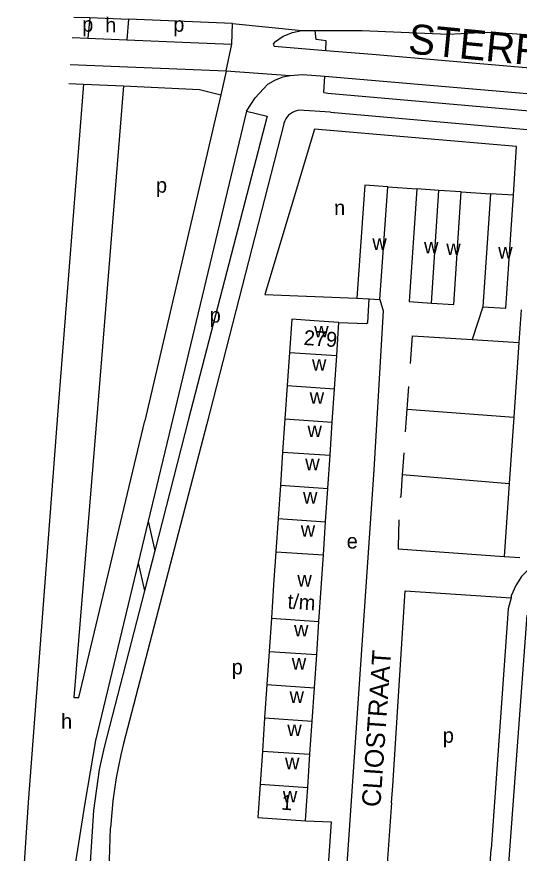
# Model space of a CAD drawing. Extents: x 161773 to 163836, y 384796 to 386521.
# Drawn here: x 161920.3 to 162054.9, y 386283.2 to 386507.1 of the extents above; entities that cross this region are included whole.
import ezdxf

# ---------------------------------------------------------------- set-up
doc = ezdxf.new("R2010")
doc.units = 0
for name, color, linetype in [('BLT_Basislijn', 7, 'Continuous'), ('BLT_Bebouwing', 7, 'Continuous'), ('BLT_Centroide', 7, 'Continuous'), ('BLT_Huisnummer_reeks', 7, 'Continuous'), ('BLT_Onderverdeling_panden', 7, 'Continuous'), ('BLT_Straatnaam', 7, 'Continuous'), ('BLT_Straatnaam_hoofdweg', 7, 'Continuous'), ('BLT_Vlakafsluiter', 7, 'Continuous')]:
    doc.layers.add(name, color=color, linetype=linetype)

msp = doc.modelspace()

# ---------------------------------------------------------------- linework, layer by layer
at = {"layer": 'BLT_Basislijn'}
for p, q in [((161935.63, 386507.05), (161939.87, 386506.89)), ((161939.87, 386506.89), (161939.37, 386501.38)), ((161939.87, 386506.89), (161950.28, 386506.48)), ((161950.28, 386506.48), (161949.83, 386500.95)), ((161935.17, 386501.56), (161939.37, 386501.38)), ((161939.37, 386501.38), (161949.83, 386500.95)), ((161949.83, 386500.95), (161966.84, 386500.23)), ((161934.64, 386494.33), (161976.44, 386492.65)), ((161976.43, 386492.6), (161974.94, 386486.21)), ((161976.44, 386492.65), (161976.43, 386492.6)), ((161996.87, 386491.69), (162002.79, 386491.19)), ((161938.19, 386489.12), (161931.36, 386401.7)), ((161934.27, 386489.3), (161938.19, 386489.12)), ((161938.19, 386489.12), (161948.92, 386488.61)), ((162002.53, 386486.84), (162002.79, 386491.19)), ((162002.79, 386491.19), (162077.21, 386484.92)), ((161948.92, 386488.61), (161941.93, 386402.27)), ((161974.94, 386486.21), (161954.62, 386399)), ((161981.83, 386481.82), (161962.23, 386399.97)), ((161987.41, 386480.49), (161966.35, 386399.44)), ((161981.83, 386481.82), (161987.41, 386480.49)), ((162004.3, 386481.62), (161995.88, 386482.11)), ((162004.3, 386481.62), (162059.08, 386476.74)), ((161991.85, 386478.49), (161971.19, 386398.18)), ((162019.69, 386461.58), (162027.41, 386461.04)), ((162039.33, 386460.24), (162047.16, 386459.74)), ((162045.16, 386429.52), (162042.3, 386420.71)), ((162055.37, 386428.67), (162054.77, 386419.92)), ((162054.77, 386419.92), (162053.39, 386399.97)), ((162024.87, 386402.1), (162025.32, 386408.17)), ((162024.42, 386396.04), (162024.87, 386402.1)), ((162024.87, 386402.1), (162053.39, 386399.97)), ((161931.36, 386401.7), (161923.36, 386296.84)), ((162053.39, 386399.97), (162052.17, 386382.22)), ((161971.19, 386398.18), (161948.93, 386312.61)), ((162024, 386390.4), (162023.64, 386385.56)), ((162023.55, 386384.58), (162023.13, 386378.77)), ((162023.64, 386385.56), (162023.55, 386384.58)), ((162023.55, 386384.58), (162052.17, 386382.22)), ((162052.17, 386382.22), (162050.83, 386362.68)), ((162023.11, 386378.47), (162023.13, 386378.77)), ((161955.54, 386372.11), (161957.28, 386364.22)), ((162050.83, 386362.68), (162052.3, 386362.57)), ((162052.3, 386362.57), (162054.99, 386362.39)), ((161952.87, 386360.99), (161954.52, 386353.5)), ((162021.04, 386301.32), (162024.35, 386353.45)), ((162024.35, 386353.45), (162052.68, 386351.64)), ((162052.68, 386351.64), (162051.91, 386348.65)), ((162051.91, 386348.65), (162047.33, 386284.36)), ((162047.33, 386216.15), (162056.95, 386346.98)), ((162020.71, 386296.7), (162021.04, 386301.32)), ((161923.36, 386296.84), (161920.34, 386250)), ((162020.71, 386296.7), (162019.23, 386276.2)), ((161940.86, 386294.72), (161938.16, 386250.02)), ((161997.65, 386291.95), (162004.51, 386291.67)), ((162046.61, 386274.46), (162047.33, 386284.36))]:
    msp.add_line(p, q, dxfattribs=at)
for points in [[(161978.14, 386505.3), (161950.28, 386506.48)], [(161977.91, 386499.77), (161978.14, 386505.3)], [(161989.33, 386500.37), (161991.67, 386501.9), (161994.13, 386502.88), (161996.64, 386503.49)], [(161996.64, 386503.49), (162000.27, 386503.49)], [(162003.09, 386498.13), (162003.2, 386500.72), (162000.49, 386501.01), (162000.27, 386503.49)], [(162000.27, 386503.49), (162012.82, 386503.49), (162035.86, 386502.45), (162046.31, 386502.96)], [(162046.31, 386502.96), (162053, 386502.69), (162070.25, 386501.37), (162091.27, 386497.24), (162112.99, 386495.59)], [(161989.33, 386500.37), (161989.01, 386499.75), (161989.28, 386499.25)], [(161966.84, 386500.23), (161977.91, 386499.77)], [(161989.28, 386499.25), (162003.09, 386498.13)], [(162003.09, 386498.13), (162015.49, 386497.13), (162077.31, 386491.77)], [(161991.66, 386491.04), (161993.58, 386491.45)], [(161993.58, 386491.45), (161996.87, 386491.69)], [(161981.83, 386481.82), (161984.21, 386485.46), (161987.6, 386489.1), (161989.63, 386490.24), (161991.66, 386491.04)], [(161948.92, 386488.61), (161969.23, 386487.67), (161974.94, 386486.21)], [(162002.53, 386486.84), (162003.63, 386486.7), (162166.71, 386472.43)], [(161995.88, 386482.11), (161995.27, 386481.99), (161994.69, 386481.79), (161994.13, 386481.52), (161993.61, 386481.17), (161993.14, 386480.77), (161992.73, 386480.3), (161992.38, 386479.79), (161992.1, 386479.24), (161991.89, 386478.65), (161991.85, 386478.49)], [(162053.31, 386459.34), (162054.17, 386472.42), (162000.07, 386477.05), (161986.77, 386432.78), (162011.4, 386431.85)], [(162006.61, 386425.32), (162013.98, 386425.05), (162014.3, 386425.26), (162014.66, 386431.62)], [(162017.57, 386431.41), (162018.44, 386428.43), (162015.98, 386385.88), (162008.12, 386271.26), (162010.3, 386267.83)], [(162025.79, 386414.35), (162026.33, 386421.71), (162042.3, 386420.71)], [(162042.3, 386420.71), (162054.77, 386419.92)], [(161941.93, 386402.27), (161935.67, 386324.92), (161937.01, 386324.92), (161954.62, 386399)], [(161962.23, 386399.97), (161955.54, 386372.11)], [(161966.35, 386399.44), (161957.28, 386364.22)], [(161955.54, 386372.11), (161952.87, 386360.99)], [(162022.66, 386372.5), (162022.45, 386365.24), (162022.45, 386364.74), (162050.83, 386362.68)], [(161957.28, 386364.22), (161954.52, 386353.5)], [(162067.88, 386362.97), (162063.25, 386362.18), (162060.78, 386361.41), (162058.37, 386359.89), (162056.99, 386358.79), (162055.44, 386357.35), (162053.96, 386354.94), (162052.75, 386352.1), (162052.68, 386351.64)], [(161952.87, 386360.99), (161941.43, 386313.38), (161938.55, 386296.64)], [(161954.52, 386353.5), (161943.74, 386311.65), (161942.39, 386305.68), (161940.86, 386294.72)], [(161948.93, 386312.61), (161948.21, 386309.57), (161947.57, 386306.52), (161947, 386303.45), (161946.52, 386300.37), (161946.11, 386297.27), (161945.78, 386294.17), (161945.53, 386291.06), (161945.47, 386290.03)], [(161938.55, 386296.64), (161933.17, 386262.33), (161931.74, 386250)], [(162002.91, 386268.41), (161944.89, 386272.91), (161945.47, 386290.03)], [(162004.51, 386291.67), (162002.91, 386268.41)]]:
    msp.add_lwpolyline(points, dxfattribs=at)
at = {"layer": 'BLT_Bebouwing'}
for p, q in [((162013.52, 386462.01), (162011.4, 386431.85)), ((162019.69, 386461.58), (162013.52, 386462.01)), ((162017.57, 386431.41), (162019.69, 386461.58)), ((162033.37, 386460.64), (162027.41, 386461.04)), ((162039.33, 386460.24), (162033.37, 386460.64)), ((162053.31, 386459.34), (162047.16, 386459.74)), ((162011.4, 386431.85), (162014.66, 386431.62)), ((162014.66, 386431.62), (162017.57, 386431.41)), ((161993.34, 386417.29), (161992.74, 386408.4)), ((162005.42, 386407.53), (162006.01, 386416.43)), ((161992.74, 386408.4), (161992.14, 386399.51)), ((162004.82, 386398.64), (162005.42, 386407.53)), ((161992.14, 386399.51), (161991.53, 386390.61)), ((162004.22, 386389.75), (162004.82, 386398.64)), ((161991.53, 386390.61), (161990.93, 386381.73)), ((162003.62, 386380.86), (162004.22, 386389.75)), ((161990.93, 386381.73), (161990.33, 386372.84)), ((162003.03, 386371.97), (162003.62, 386380.86)), ((161990.33, 386372.84), (161989.72, 386363.95)), ((162002.43, 386363.08), (162003.03, 386371.97)), ((161989.72, 386363.95), (161989.12, 386355.05)), ((162001.83, 386354.19), (162002.43, 386363.08)), ((161989.12, 386355.05), (161988.52, 386346.17)), ((162001.24, 386345.3), (162001.83, 386354.19)), ((161988.52, 386346.17), (161987.91, 386337.28)), ((162000.64, 386336.41), (162001.24, 386345.3)), ((161987.91, 386337.28), (161987.31, 386328.39)), ((162000.04, 386327.52), (162000.64, 386336.41)), ((161987.31, 386328.39), (161986.71, 386319.49)), ((161999.45, 386318.63), (162000.04, 386327.52)), ((161986.71, 386319.49), (161986.1, 386310.61)), ((161998.85, 386309.74), (161999.45, 386318.63)), ((161986.1, 386310.61), (161985.5, 386301.72)), ((161998.25, 386300.85), (161998.85, 386309.74)), ((161998.01, 386297.24), (161998.25, 386300.85))]:
    msp.add_line(p, q, dxfattribs=at)
for points in [[(162027.41, 386461.04), (162025.4, 386430.88), (162031.36, 386430.48)], [(162031.36, 386430.48), (162037.32, 386430.09), (162039.33, 386460.24)], [(162047.16, 386459.74), (162045.16, 386429.52)], [(162045.16, 386429.52), (162051.32, 386429.11), (162053.31, 386459.34)], [(162006.61, 386425.32), (162000, 386425.76), (161993.95, 386426.18), (161993.34, 386417.29)], [(162006.01, 386416.43), (162006.42, 386422.46), (162006.61, 386425.32)], [(161985.5, 386301.72), (161984.89, 386292.82), (161997.65, 386291.95)], [(161997.65, 386291.95), (161998.01, 386297.24)]]:
    msp.add_lwpolyline(points, dxfattribs=at)
at = {"layer": 'BLT_Onderverdeling_panden'}
for p, q in [((162031.36, 386430.48), (162033.37, 386460.64)), ((161993.34, 386417.29), (162006.01, 386416.43)), ((161992.74, 386408.4), (162005.42, 386407.53)), ((161992.14, 386399.51), (162004.82, 386398.64)), ((161991.53, 386390.61), (162004.22, 386389.75)), ((161990.93, 386381.73), (162003.62, 386380.86)), ((161990.33, 386372.84), (162003.03, 386371.97)), ((161989.72, 386363.95), (162002.43, 386363.08)), ((161988.52, 386346.17), (162001.24, 386345.3)), ((161987.91, 386337.28), (162000.64, 386336.41)), ((161987.31, 386328.39), (162000.04, 386327.52)), ((161986.71, 386319.49), (161999.45, 386318.63)), ((161986.1, 386310.61), (161998.85, 386309.74)), ((161985.5, 386301.72), (161998.25, 386300.85))]:
    msp.add_line(p, q, dxfattribs=at)
at = {"layer": 'BLT_Vlakafsluiter'}
for p, q in [((161978.14, 386505.3), (161996.64, 386503.49)), ((161976.44, 386492.65), (161977.91, 386499.77)), ((161976.44, 386492.65), (161993.58, 386491.45))]:
    msp.add_line(p, q, dxfattribs=at)

# ---------------------------------------------------------------- texts
at = {"layer": 'BLT_Centroide'}
for s, p in [('h', (161944.01, 386502.92)), ('p', (161937.86, 386503.11)), ('p', (161962.25, 386503.11)), ('p', (161957.62, 386460.05)), ('n', (162005.31, 386454.03)), ('w', (162015.55, 386444.72)), ('w', (162029.38, 386443.77)), ('w', (162035.34, 386443.36)), ('w', (162049.23, 386442.42)), ('p', (161971.99, 386425.27)), ('w', (161999.98, 386421.31)), ('w', (161999.38, 386412.41)), ('w', (161998.77, 386403.53)), ('w', (161998.18, 386394.62)), ('w', (161997.58, 386385.75)), ('w', (161996.98, 386376.84)), ('w', (161996.38, 386367.97)), ('e', (162008.67, 386364.8)), ('w', (161995.47, 386354.62)), ('w', (161994.58, 386341.28)), ('w', (161993.98, 386332.41)), ('p', (161977.9, 386331.13)), ('w', (161993.38, 386323.5)), ('h', (161932.21, 386316.59)), ('w', (161992.77, 386314.62)), ('p', (162034.4, 386312.81)), ('w', (161992.17, 386305.72)), ('w', (161991.58, 386296.84))]:
    msp.add_text(s, height=4, dxfattribs=at).set_placement(p)
at = {"layer": 'BLT_Huisnummer_reeks'}
for s, rotation, p in [('279', 356.1133, (161997.08, 386419.3)), ('t/m', 356.1153, (161992.76, 386348.75)), ('1', 356.1174, (161991.06, 386294.93))]:
    msp.add_text(s, height=4, rotation=rotation, dxfattribs=at).set_placement(p)
at = {"layer": 'BLT_Straatnaam'}
msp.add_text('CLIOSTRAAT', height=5, rotation=86.0379, dxfattribs=at).set_placement((162017.68, 386295.49))
at = {"layer": 'BLT_Straatnaam_hoofdweg'}
msp.add_text('STERRENLAAN', height=7.9999, rotation=354.4661, dxfattribs=at).set_placement((162024.93, 386497.35))

doc.saveas('drawing.dxf')
